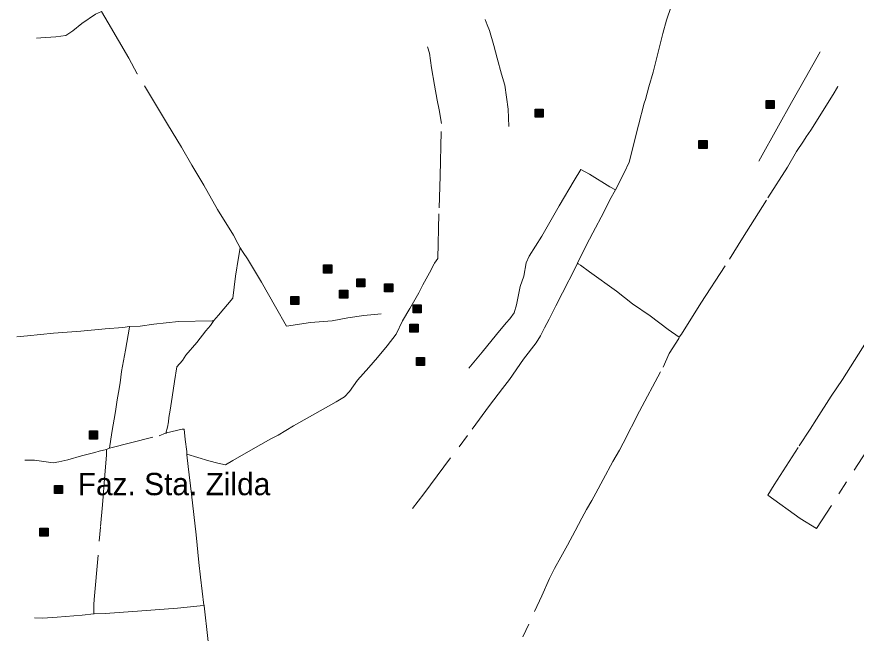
# Model space of a CAD drawing. Extents: x 393.5 to 446.9, y 8064.8 to 8120.4.
# Drawn here: x 432.95 to 438.96, y 8081.77 to 8086.18 of the extents above; entities that cross this region are included whole.
import ezdxf

# ---------------------------------------------------------------- set-up
doc = ezdxf.new("R2010")
doc.units = 0
doc.header["$LTSCALE"] = 0.064
doc.linetypes.add('DOT_DASHED', pattern=[7.7, 5, -1.2, 0.3, -1.2])
doc.layers.add('2', color=7, linetype='Continuous', lineweight=25)
doc.layers.add('22', color=7, linetype='DOT_DASHED', lineweight=13)
doc.layers.add('61', color=7, linetype='Continuous')

msp = doc.modelspace()

# ---------------------------------------------------------------- hatches: boundary and pattern name
at = {"layer": '2'}
for points in [[(438.3129, 8085.583), (438.3709, 8085.583), (438.3709, 8085.525), (438.3129, 8085.525)], [(436.6586, 8085.5205), (436.7166, 8085.5205), (436.7166, 8085.4625), (436.6586, 8085.4625)], [(437.8315, 8085.2968), (437.8895, 8085.2968), (437.8895, 8085.2388), (437.8315, 8085.2388)], [(435.1436, 8084.4048), (435.2016, 8084.4048), (435.2016, 8084.3468), (435.1436, 8084.3468)], [(435.38, 8084.3058), (435.438, 8084.3058), (435.438, 8084.2478), (435.38, 8084.2478)], [(435.5798, 8084.2694), (435.6378, 8084.2694), (435.6378, 8084.2114), (435.5798, 8084.2114)], [(435.2579, 8084.2244), (435.3159, 8084.2244), (435.3159, 8084.1664), (435.2579, 8084.1664)], [(434.9088, 8084.1795), (434.9668, 8084.1795), (434.9668, 8084.1215), (434.9088, 8084.1215)], [(435.7844, 8084.1202), (435.8424, 8084.1202), (435.8424, 8084.0622), (435.7844, 8084.0622)], [(435.7618, 8083.9809), (435.8198, 8083.9809), (435.8198, 8083.9229), (435.7618, 8083.9229)], [(435.8084, 8083.7418), (435.8664, 8083.7418), (435.8664, 8083.6838), (435.8084, 8083.6838)], [(433.466, 8083.2154), (433.524, 8083.2154), (433.524, 8083.1574), (433.466, 8083.1574)], [(433.216, 8082.8259), (433.274, 8082.8259), (433.274, 8082.7679), (433.216, 8082.7679)], [(433.1115, 8082.5193), (433.1695, 8082.5193), (433.1695, 8082.4613), (433.1115, 8082.4613)]]:
    msp.add_hatch(color=256, dxfattribs=at).paths.add_polyline_path(points)

# ---------------------------------------------------------------- linework, layer by layer
for points in [[(438.3129, 8085.583), (438.3709, 8085.583), (438.3709, 8085.525), (438.3129, 8085.525)], [(436.6586, 8085.5205), (436.7166, 8085.5205), (436.7166, 8085.4625), (436.6586, 8085.4625)], [(437.8315, 8085.2968), (437.8895, 8085.2968), (437.8895, 8085.2388), (437.8315, 8085.2388)], [(435.1436, 8084.4048), (435.2016, 8084.4048), (435.2016, 8084.3468), (435.1436, 8084.3468)], [(435.38, 8084.3058), (435.438, 8084.3058), (435.438, 8084.2478), (435.38, 8084.2478)], [(435.5798, 8084.2694), (435.6378, 8084.2694), (435.6378, 8084.2114), (435.5798, 8084.2114)], [(435.2579, 8084.2244), (435.3159, 8084.2244), (435.3159, 8084.1664), (435.2579, 8084.1664)], [(434.9088, 8084.1795), (434.9668, 8084.1795), (434.9668, 8084.1215), (434.9088, 8084.1215)], [(435.7844, 8084.1202), (435.8424, 8084.1202), (435.8424, 8084.0622), (435.7844, 8084.0622)], [(435.7618, 8083.9809), (435.8198, 8083.9809), (435.8198, 8083.9229), (435.7618, 8083.9229)], [(435.8084, 8083.7418), (435.8664, 8083.7418), (435.8664, 8083.6838), (435.8084, 8083.6838)], [(433.466, 8083.2154), (433.524, 8083.2154), (433.524, 8083.1574), (433.466, 8083.1574)], [(433.216, 8082.8259), (433.274, 8082.8259), (433.274, 8082.7679), (433.216, 8082.7679)], [(433.1115, 8082.5193), (433.1695, 8082.5193), (433.1695, 8082.4613), (433.1115, 8082.4613)]]:
    msp.add_lwpolyline(points, close=True, dxfattribs=at)
at = {"layer": '22'}
for points in [[(437.4476, 8085.5904), (437.4718, 8085.6816), (437.5035, 8085.7868), (437.5728, 8086.0637), (437.5978, 8086.1591), (437.6315, 8086.256), (437.6403, 8086.313), (437.6515, 8086.3429)], [(434.5456, 8084.5271), (434.5284, 8084.5596), (434.4971, 8084.6172), (434.3827, 8084.8009), (434.2854, 8084.9769), (434.1997, 8085.1193), (434.1263, 8085.2497), (434.0258, 8085.4129), (433.8089, 8085.7737), (433.7488, 8085.8865), (433.5996, 8086.1385), (433.5518, 8086.2201), (433.5106, 8086.2025), (433.4116, 8086.1337), (433.3473, 8086.0825), (433.2978, 8086.0489), (433.2253, 8086.0393), (433.1181, 8086.0313), (433.0876, 8086.0305)], [(436.4704, 8085.3976), (436.465, 8085.5204), (436.4419, 8085.6934), (436.4169, 8085.7713), (436.3866, 8085.8872), (436.3616, 8085.9771), (436.3314, 8086.0833), (436.3135, 8086.1249), (436.2996, 8086.1623)], [(435.9348, 8084.4139), (435.9366, 8084.4173), (435.9601, 8084.4514), (435.9699, 8084.8148), (435.977, 8085.0404), (435.9877, 8085.4193), (435.9718, 8085.517), (435.9575, 8085.5845), (435.9379, 8085.6935), (435.9147, 8085.8181), (435.9005, 8085.9219), (435.888, 8085.9668)], [(438.2607, 8085.1477), (438.4009, 8085.4003), (438.4938, 8085.5676), (438.5933, 8085.7463), (438.6995, 8085.9313)], [(438.6, 8085.3227), (438.6319, 8085.3704), (438.7917, 8085.626), (438.8232, 8085.6783), (438.8267, 8085.6863)], [(437.233, 8084.9424), (437.2951, 8085.0659), (437.3306, 8085.1402), (437.3983, 8085.4053), (437.438, 8085.5649), (437.4476, 8085.5904)], [(437.6899, 8083.887), (437.7053, 8083.9096), (437.8458, 8084.1305), (438.0494, 8084.4453), (438.1437, 8084.5976), (438.325, 8084.8846), (438.4655, 8085.1055), (438.5302, 8085.2165), (438.58, 8085.2921), (438.6, 8085.3227)], [(436.1826, 8083.6642), (436.278, 8083.7803), (436.3808, 8083.9072), (436.4518, 8083.9907), (436.478, 8084.0197), (436.5079, 8084.0614), (436.5238, 8084.1186), (436.5519, 8084.251), (436.5762, 8084.3253), (436.593, 8084.4197), (436.6154, 8084.4668), (436.707, 8084.6101), (436.8304, 8084.8277), (436.9369, 8085.0091), (436.9855, 8085.0889), (437.0472, 8085.0544), (437.193, 8084.9638), (437.233, 8084.9424)], [(437.233, 8084.9424), (437.1926, 8084.8717), (437.1496, 8084.7828), (437.0711, 8084.6341), (437.0225, 8084.5452), (436.9615, 8084.4175)], [(434.358, 8084.0057), (434.3893, 8084.0441), (434.4929, 8084.1671), (434.5127, 8084.3239), (434.5341, 8084.4583), (434.5456, 8084.5271)], [(435.2045, 8084.0044), (435.0486, 8083.9924), (434.8771, 8083.9652), (434.798, 8084.1044), (434.6974, 8084.2804), (434.5977, 8084.4476), (434.568, 8084.494), (434.5456, 8084.5271)], [(439.8506, 8084.3427), (439.7947, 8084.257), (439.7143, 8084.1286), (439.5969, 8083.9489), (439.4654, 8083.7478), (439.2959, 8083.4793), (439.1155, 8083.2032), (438.6734, 8082.5174), (438.5567, 8082.5877), (438.3251, 8082.7544), (438.3692, 8082.8293), (438.5496, 8083.1085), (438.6284, 8083.2277), (438.6741, 8083.2996), (438.7789, 8083.4655), (438.8593, 8083.5848), (439.1673, 8084.0721), (439.2761, 8084.2372), (439.3486, 8084.3535), (439.4092, 8084.4536), (439.4218, 8084.475)], [(435.7792, 8082.6608), (435.8615, 8082.766), (436.2073, 8083.2285), (436.3316, 8083.3981), (436.4232, 8083.5196), (436.4737, 8083.5831), (436.5755, 8083.7291), (436.6653, 8083.847), (436.697, 8083.8978), (436.7241, 8083.955), (436.7596, 8084.0166), (436.8064, 8084.111), (436.855, 8084.2053), (436.9465, 8084.3867), (436.9612, 8084.4169), (436.9615, 8084.4175)], [(435.8508, 8084.2564), (435.854, 8084.2623), (435.9022, 8084.3488), (435.9348, 8084.4139)], [(437.6899, 8083.887), (437.612, 8083.9423), (437.4811, 8084.0403), (437.3559, 8084.1255), (437.24, 8084.2162), (437.0475, 8084.3559), (436.9821, 8084.403), (436.9669, 8084.4137), (436.9621, 8084.4171), (436.9615, 8084.4175)], [(434.1633, 8083.0501), (434.3201, 8083.001), (434.386, 8082.9837), (434.4413, 8082.9716), (434.493, 8083.0044), (434.6214, 8083.0788), (434.7658, 8083.1584), (434.8175, 8083.1861), (434.9272, 8083.251), (435.118, 8083.36), (435.2321, 8083.424), (435.2937, 8083.4595), (435.3275, 8083.4976), (435.3864, 8083.5789), (435.4666, 8083.6706), (435.529, 8083.7416), (435.5977, 8083.8255), (435.6637, 8083.9085), (435.7083, 8084.0054), (435.7613, 8084.0927), (435.797, 8084.155), (435.8255, 8084.2052), (435.8508, 8084.2564)], [(435.5557, 8084.054), (435.4304, 8084.0428), (435.3166, 8084.0252), (435.2045, 8084.0044)], [(432.9458, 8083.8888), (433.0233, 8083.8977), (433.2096, 8083.9153), (433.4042, 8083.9313), (433.5797, 8083.9465), (433.705, 8083.9577), (433.7528, 8083.9641)], [(433.6104, 8083.0911), (433.6258, 8083.2041), (433.6522, 8083.3545), (433.6654, 8083.4393), (433.6753, 8083.4905), (433.6868, 8083.5593), (433.6967, 8083.6409), (433.724, 8083.7937), (433.752, 8083.9597), (433.7521, 8083.9602), (433.7528, 8083.9641)], [(433.7528, 8083.9641), (433.8304, 8083.9673), (433.9276, 8083.9801), (434.1048, 8084.0001), (434.3458, 8084.0051), (434.356, 8084.0056), (434.3578, 8084.0057), (434.358, 8084.0057)], [(434.157, 8083.7593), (434.2359, 8083.8483), (434.3003, 8083.9331), (434.3332, 8083.9715), (434.358, 8084.0057)], [(437.2877, 8083.1269), (437.4065, 8083.3578), (437.5744, 8083.673), (437.6192, 8083.7696), (437.6872, 8083.8774), (437.6899, 8083.887)], [(434.0357, 8083.3118), (434.0449, 8083.3641), (434.0597, 8083.4569), (434.0762, 8083.5705), (434.091, 8083.6745), (434.1323, 8083.7209), (434.157, 8083.7593)], [(434.0141, 8083.2), (434.0261, 8083.242), (434.0314, 8083.2801), (434.0357, 8083.3118)], [(434.0188, 8083.2012), (434.1295, 8083.2288), (434.1444, 8083.2288), (434.1526, 8083.1552), (434.1625, 8083.0688), (434.1633, 8083.0501)], [(433.6104, 8083.0911), (433.9654, 8083.1815), (434.0105, 8083.1986), (434.0141, 8083.2)], [(434.0141, 8083.2), (434.015, 8083.2002), (434.0188, 8083.2012)], [(436.3228, 8081.2058), (436.3941, 8081.3595), (436.7052, 8082.0338), (436.7615, 8082.1593), (436.7964, 8082.2302), (436.8424, 8082.3112), (436.8889, 8082.3981), (436.9453, 8082.5011), (436.9934, 8082.5912), (437.0265, 8082.6523), (437.063, 8082.7167), (437.094, 8082.7688), (437.1454, 8082.867), (437.215, 8082.9958), (437.2631, 8083.0778), (437.2877, 8083.1269)], [(433.0039, 8083.0067), (433.0715, 8083.0067), (433.2067, 8082.9875), (433.2462, 8082.9935), (433.3121, 8083.0095), (433.4094, 8083.0367), (433.505, 8083.0623), (433.5369, 8083.0713), (433.5662, 8083.0787), (433.5889, 8083.0835), (433.589, 8083.0835), (433.5891, 8083.0835)], [(433.4977, 8081.9048), (433.4977, 8081.972), (433.4994, 8082.0072), (433.5456, 8082.532), (433.5588, 8082.6856), (433.5637, 8082.7448), (433.5719, 8082.8411), (433.5884, 8083.0443), (433.5891, 8083.0831), (433.5891, 8083.0835)], [(433.6104, 8083.0911), (433.607, 8083.091), (433.6069, 8083.091), (433.589, 8083.0835)], [(434.2865, 8081.9672), (434.2623, 8082.1686), (434.2498, 8082.2724), (434.2293, 8082.4723), (434.1963, 8082.7621), (434.1723, 8082.9601), (434.1638, 8083.045), (434.1633, 8083.0501)], [(433.4995, 8081.9049), (433.5785, 8081.908), (433.8094, 8081.9256), (434.0965, 8081.9471), (434.2587, 8081.9627), (434.2865, 8081.9672)], [(434.4196, 8080.6837), (434.4043, 8080.848), (434.3911, 8080.9728), (434.3763, 8081.1344), (434.3458, 8081.4472), (434.3137, 8081.7296), (434.287, 8081.9629), (434.2867, 8081.9654), (434.2865, 8081.9672)], [(433.0733, 8081.8766), (433.1317, 8081.8744), (433.2356, 8081.8808), (433.4137, 8081.8968), (433.4977, 8081.9048)], [(433.4977, 8081.9048), (433.4993, 8081.9049), (433.4995, 8081.9049)]]:
    msp.add_lwpolyline(points, dxfattribs=at)

# ---------------------------------------------------------------- texts
at = {"layer": '61'}
msp.add_text('Faz. Sta. Zilda ', height=0.16, dxfattribs=at).set_placement((433.3822, 8082.7552))

doc.saveas('drawing.dxf')
